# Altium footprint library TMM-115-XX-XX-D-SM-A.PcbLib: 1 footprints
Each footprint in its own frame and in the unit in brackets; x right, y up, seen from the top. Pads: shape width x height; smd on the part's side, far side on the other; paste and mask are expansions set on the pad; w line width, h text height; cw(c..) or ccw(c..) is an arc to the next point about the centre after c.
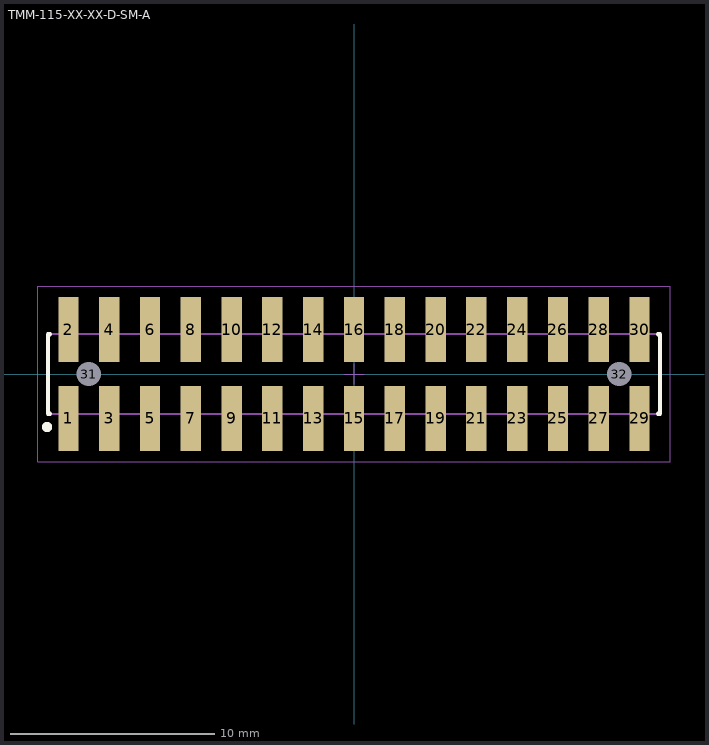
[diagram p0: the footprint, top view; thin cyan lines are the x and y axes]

## TMM-115-XX-XX-D-SM-A [mm] "2.00mm pitch, 30 pin, terminal strip; double row, w/alignment pins, SMT"
height 2.77
pads (32):
  rect 1x3.2 smd mask+0: 1(-14,-2.178) 2(-14,2.178) 3(-12,-2.178) 4(-12,2.178) 5(-10,-2.178) 6(-10,2.178) 7(-8,-2.178) 8(-8,2.178) 9(-6,-2.178) 10(-6,2.178) 11(-4,-2.178) 12(-4,2.178) 13(-2,-2.178) 14(-2,2.178) 15(0,-2.178) 16(0,2.178) 17(2,-2.178) 18(2,2.178) 19(4,-2.178) 20(4,2.178) 21(6,-2.178) 22(6,2.178) 23(8,-2.178) 24(8,2.178) 25(10,-2.178) 26(10,2.178) 27(12,-2.178) 28(12,2.178) 29(14,-2.178) 30(14,2.178)
  round 1 hole 1.2 unplated mask+0: 31(-13.006,0) 32(13.006,0)
Top Overlay:
  circle w0.25: c-15.05,-2.6 r0.125
  lines w0.2: -14.9,-1.95 -15,-1.95 -15,1.95 -14.9,1.95 ; 14.9,-1.95 15,-1.95 15,1.95 14.9,1.95
Mechanical 12:
  lines w0.001: -15,-1.95 15,-1.95 15,1.95 -15,1.95 -15,-1.95
Mechanical 13:
  circle w0.1: c-14.126,-2.752 r0.127
  lines w0.1: -15,-1.95 15,-1.95 15,1.95 -15,1.95 -15,-1.95
  text ".Designator" at 0,-0.127 h1.52
Mechanical 15:
  lines w0.05: -0.5,0 0.5,0 ; 0,-0.5 0,0.5 ; -15.5,-4.3 15.5,-4.3 15.5,4.3 -15.5,4.3 -15.5,-4.3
